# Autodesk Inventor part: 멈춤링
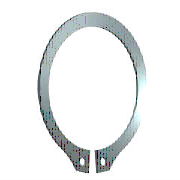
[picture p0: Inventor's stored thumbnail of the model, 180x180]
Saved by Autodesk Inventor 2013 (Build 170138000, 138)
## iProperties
IsCustomPart: 1
Company: 한국ATC센터
Created: 2014-10
Part Number: 멈춤링
Material: 강철, 연강
Description: 리테이닝 링(C형)
Document SubType Name: Modeling
Standard: KS B 1336
Designer: 한국ATC센터
Standards Organization: KS
Language: ko-KR
Size Designation: 25 x 1.2
Categories: <MemberInstance><Categories><Category DisplayName="샤프트 부품" InternalName="7f7aeb1f-a693-4053-b835-cee3144e0d98" Mnemonic="SHFT"><Category DisplayName="써클립" Inter
Density: 7.86 g/cm^3
Mass: 2.3429 g
Surface Area: 7.2498 cm^2
Volume: 0.298079 cm^3
Author: KYOUNG IL JANG
Revision Number: 1
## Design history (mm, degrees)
sketch "스케치1"
  geometry: L1 (-6, 0)-(6, 0) reference; L2 (0, 20.189)-(0, -80.536) reference; L3 (-48.09, 0)-(48.09, 0) reference; L4 (-0.5, -24.44)-(-0.5, -28.74); L5 (-0.5, -6.54)-(-0.5, -13.29); L6 (-2.795, 3.1)-(3.672, 3.1); L7 (0.5, -6.54)-(0.5, -13.29); L8 (0.5, -24.44)-(0.5, -28.74); C1 r 1 at (-2, -26.606); C2 r 1 at (2, -26.606); A1 r 11.95 centre (0, -12.5) between (0.5, -24.44) and (-0.5, -24.44); A2 r 14.825 centre (0, -11.725) between (5.202, -25.608) and (-5.202, -25.608); A3 r 16.247 centre (0, -12.5) between (-2.281, -28.586) and (-0.5, -28.74); A4 r 2 centre (-2, -26.606) between (-3.952, -27.043) and (-2.281, -28.586); A5 r 2 centre (-5.903, -27.48) between (-3.952, -27.043) and (-5.202, -25.608); A6 r 2 centre (5.903, -27.48) between (5.202, -25.608) and (3.952, -27.043); A7 r 2 centre (2, -26.606) between (2.281, -28.586) and (3.952, -27.043); A8 r 16.247 centre (0, -12.5) between (0.5, -28.74) and (2.281, -28.586)
  constraints: 16 point on circle, 12 end point, 10 centre point, 9 symmetric about line, 5 point on line, 4 tangent, 3 coincident, 2 horizontal, 1 perpendicular, 1 vertical, 5 other
  dimensions: "d0" = 23.9 diameter of A1 (= ND); "d1" = 4.3 distance of L4.end L4.start (= SRB2); "d6" = 0.5 distance between parallel lines of L2 L5 (= 0.25 x SD5); "d7" = 3.1 distance between parallel lines of L6 L3 (= SRB1); "d8" = 0.775 distance of A1.centre A2.centre (= 0.25 x SRB1); "d9" = 2 radius of A4 (= SD5); "d10" = 2 radius of A5 (= SD5); "d11" = 1.5 distance from line of L4 A4.centre (= 0.75 x SD5); "d12" = 2 diameter of C1 (= SD5); "d13" = 2 diameter of C2 (= SD5); "d14" = 12.5 distance from line of A1.centre L1 (= 0.5 x WD)
extrude "본체" new body sketch "스케치1" distance "d2" = 1.2 (= SD); taper "d3" = 0 deg
workaxis "Work Axis1"
workplane "Work Plane1"
body "Solid1"
other parameters: "WD" = 25 (= WDMIN) [user parameter; used in 1 equation term], "SD" = 1.2 [user parameter; used in 1 equation term], "SRB1" = 3.1 [user parameter; used in 2 equation terms], "ND" = 23.9 [user parameter; used in 1 equation term], "SRB2" = 4.3 [user parameter; used in 1 equation term], "SD5" = 2 [user parameter; used in 6 equation terms], "d15" = 0, "d16" = 0, "d17" = 0, "d41" = 0, "d42" = 0, "WDMIN" = 25 [user parameter; used in 1 equation term], "SD3" = 23.2 [user parameter], "WDMAX" = 26 [user parameter]
